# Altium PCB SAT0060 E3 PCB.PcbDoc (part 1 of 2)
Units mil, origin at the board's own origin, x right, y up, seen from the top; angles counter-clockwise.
Board outline 3780 x 2000 mil, 4 copper layers (Top Layer, L2_GND-Plane, L3_Sig-Layer, Bottom Layer), stack 61.2 mil thick; 136 components, 78 nets, 386 pads, 150 vias.
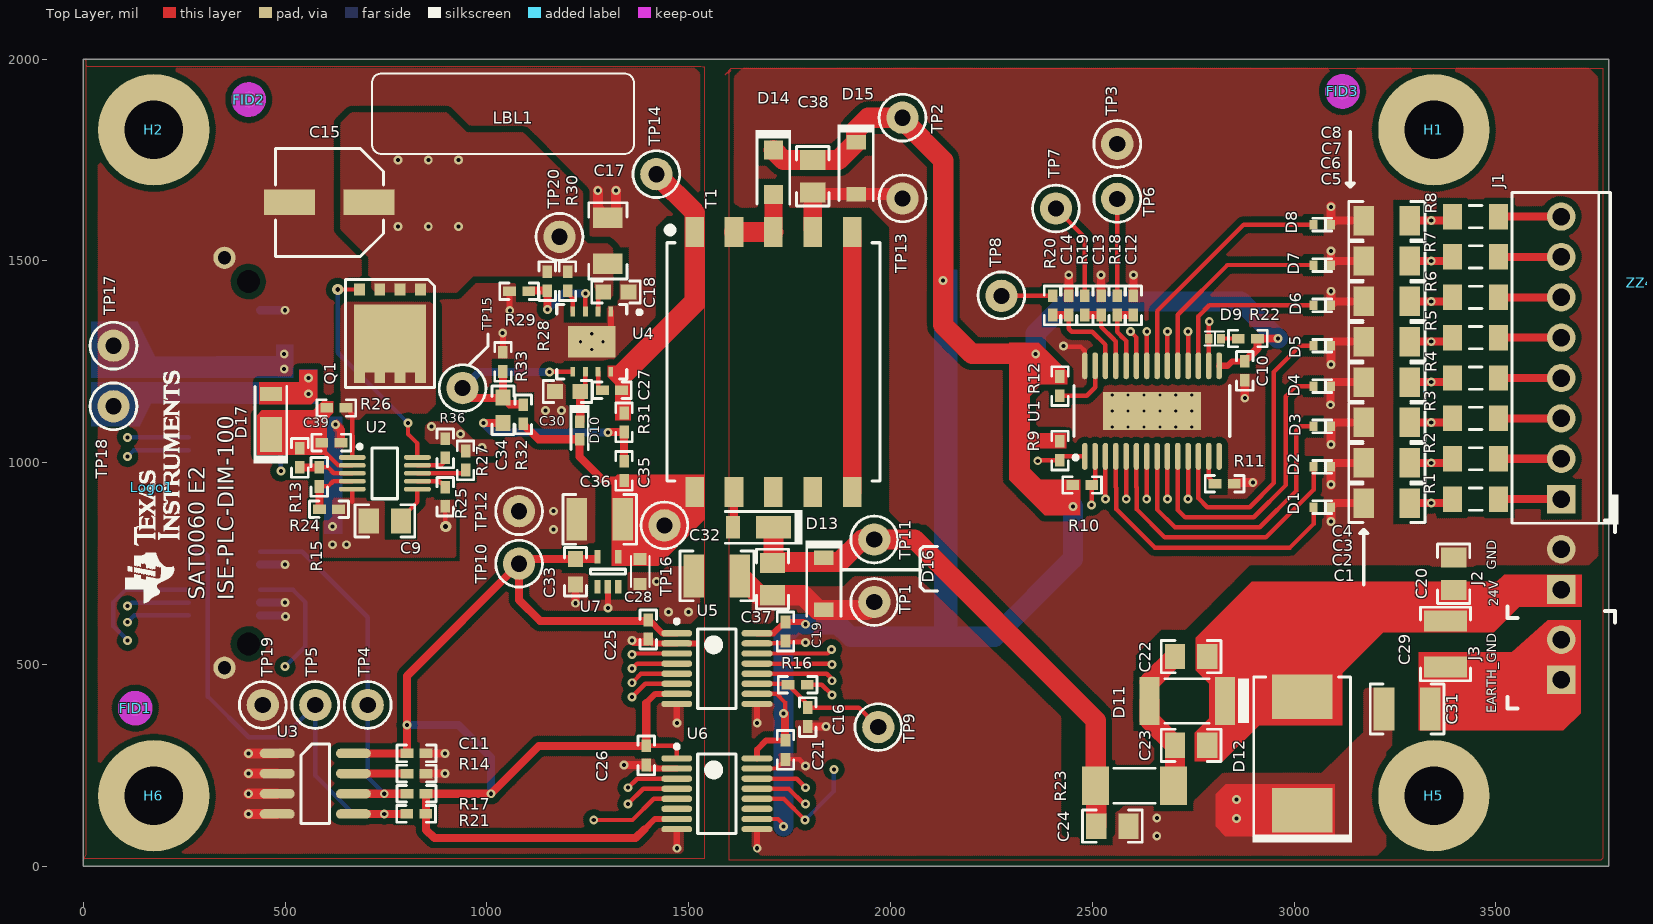
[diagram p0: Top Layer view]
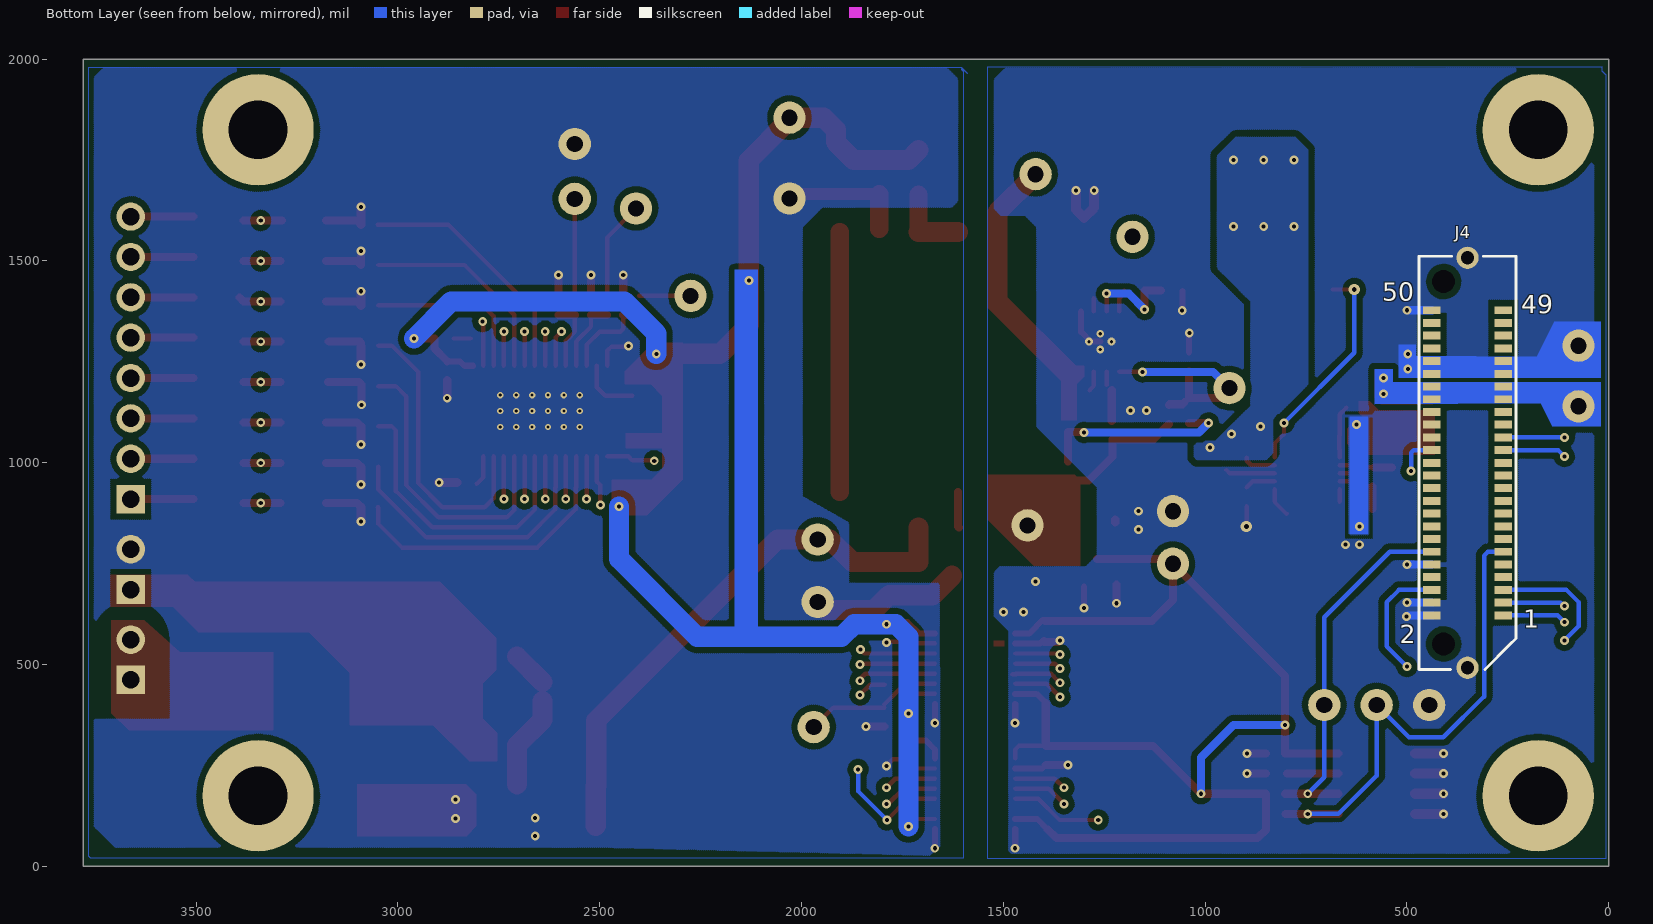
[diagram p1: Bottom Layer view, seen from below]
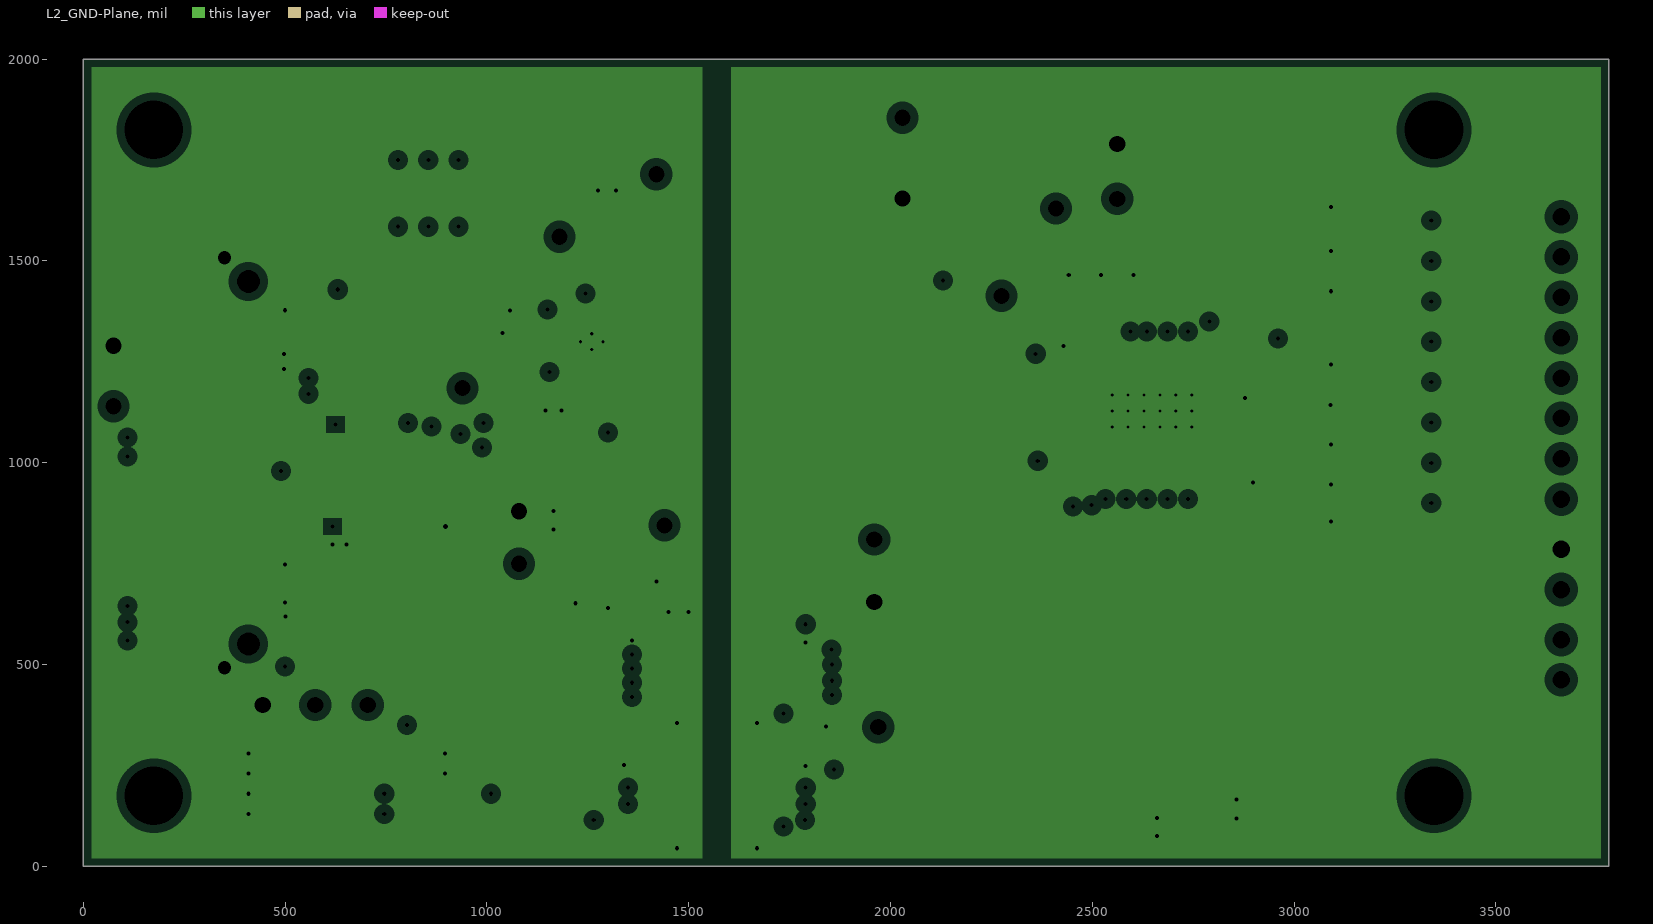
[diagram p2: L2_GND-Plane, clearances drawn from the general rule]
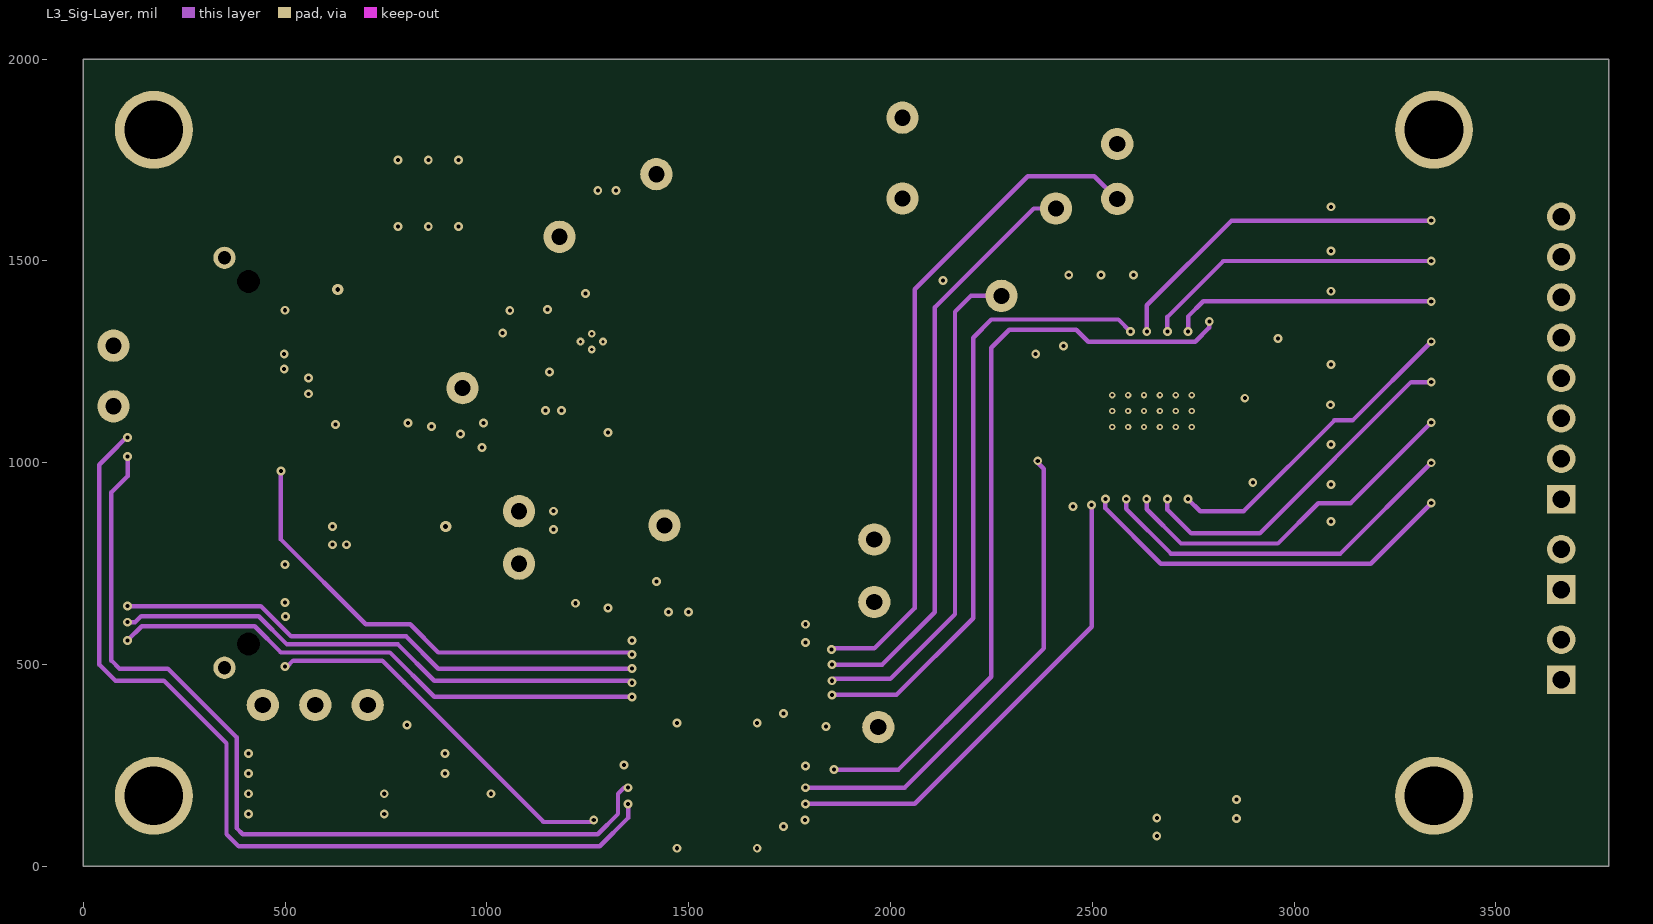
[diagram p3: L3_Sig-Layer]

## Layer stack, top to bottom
Top Layer: signal copper 1.4
Dielectric: prepreg 12.6, 370HR, Dk 4.8
L2_GND-Plane: plane copper 1.4, net (Multiple Nets)
Dielectric: core 30.4, 370HR, Dk 4.8
L3_Sig-Layer: signal copper 1.4
Dielectric: prepreg 12.6, FR-4, Dk 4.8
Bottom Layer: signal copper 1.4

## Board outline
0,0 3780,0 3780,2000 0,2000

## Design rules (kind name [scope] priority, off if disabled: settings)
AcuteAngle [All] p1: minimum=4.50000000000000E+0001 checktracksonly=FALSE
AssemblyTestPointUsage [All] p1: valid=2
Clearance "Clearance Earth ground" [InNet('EARTH_GND') vs InPolygon] p1: gap=60
Clearance "Poly Clearance" [InPolygon] p2: gap=15
Clearance Clearance_1 [All] p3: gap=7.8
Clearance Clearance_BoardEdge_MountingHoles [OnCopper and InComponentClass('Mounting Holes') vs IsKeepOut] p4: gap=20
Clearance Clearance_BoardEdge_Poly [OnCopper and InPoly vs IsKeepOut] p5: gap=20
Clearance Clearance_BoardEdge [OnCopper and Not InComponentClass('Logo') and not InComponentClass('FiducialMark') and not InRegion(1000,500,4000,800) vs IsKeepOut] p6: gap=20
ComponentClearance ComponentClearance_1 [HasFootprint('TI_Stacked_Overlay_Small_Vertical') vs InComponent('TP18')] p1: gap=0 collisioncheckmode=3 verticalgap=0 showdistances=FALSE
ComponentClearance ComponentClearance_Logo [InComponentClass(Logo) vs InComponent('TP18')] p2 off: gap=50 collisioncheckmode=3 verticalgap=0 showdistances=TRUE
ComponentClearance ComponentClearance_ScrewToNut [(HasFootprint('NY PMS 440 0025 PH')) vs (HasFootprint('Keystone_1902C'))] p3 off: gap=5 collisioncheckmode=3 verticalgap=10 showdistances=FALSE
ComponentClearance ComponentClearance_MountingHoles [InComponentClass('Mounting Holes')] p4 off: gap=250 collisioncheckmode=3 verticalgap=100000 showdistances=FALSE
ComponentClearance ComponentClearance_SmallPassives [HasFootprint('0201*') or HasFootprint('0402*') or HasFootprint('0508') or HasFootprint('0603*') or HasFootprint('0612') or HasFootprint('0805*') or HasFootprint('0815*') or HasFootprint('0830*') or HasFootprint('1206*') or HasFootprint('1210*') or HasFootprint('1808*') or HasFootprint('1812*') or HasFootprint('1825*') or HasFootprint('2010*') or HasFootprint('2220*') or HasFootprint('2225*') or HasFootprint('2512*') or HasFootprint('2728*') or HasFootprint('3518*') vs HasFootprint('0201*') or HasFootprint('0402*') or HasFootprint('0508') or HasFootprint('0603*') or HasFootprint('0612') or HasFootprint('0805*') or HasFootprint('0815*') or HasFootprint('0830*') or HasFootprint('1206*') or HasFootprint('1210*') or HasFootprint('1808*') or HasFootprint('1812*') or HasFootprint('1825*') or HasFootprint('2010*') or HasFootprint('2220*') or HasFootprint('2225*') or HasFootprint('2512*') or HasFootprint('2728*') or HasFootprint('3518*')] p5 off: gap=20 collisioncheckmode=3 verticalgap=10 showdistances=FALSE
ComponentClearance ComponentClearance_THtoSMT [IsThruComponent vs IsSMTComponent] p6 off: gap=100 collisioncheckmode=3 verticalgap=100000 showdistances=FALSE
ComponentClearance ComponentClearance_THtoTH [IsThruComponent vs IsThruComponent] p7 off: gap=118.11 collisioncheckmode=3 verticalgap=100000 showdistances=FALSE
ComponentClearance [All] p8: gap=5 collisioncheckmode=3 verticalgap=10 showdistances=TRUE
DiffPairsRouting [All] p1: maxlimit=100 minlimit=10 mostfreqgap=10 maxuncoupledlength=1000
FabricationTestPointUsage TestPointUsage [All] p1: valid=2 allowmultiple=FALSE
FabricationTestpoint Testpoint [All] p1: side=3 testpointundercomponent=TRUE minsize=40 maxsize=100 preferedsize=60 minholesize=0 maxholesize=40 preferedholesize=32 testpointgrid=1 allowsidetop=TRUE allowsidebottom=TRUE usegrid=TRUE gridtolerance=0.01
FanoutControl Fanout_LCC [IsLCC] p1: bgadir=Out bgaviamode=Centered fanoutstyle=Auto fanoutdirection=Alternating viagrid=1 // Fanout_LCC (Default Rule)
FanoutControl Fanout_BGA [IsBGA] p2: bgadir=Out bgaviamode=Centered fanoutstyle=Auto fanoutdirection=Alternating viagrid=1 // Fanout_BGA (Default Rule)
FanoutControl Fanout_Default [All] p4: bgadir=Out bgaviamode=Centered fanoutstyle=Auto fanoutdirection=Alternating viagrid=1 // Fanout_Default (Default Rule)
FanoutControl Fanout_Small [(CompPinCount < 5)] p5: bgadir=Out bgaviamode=Centered fanoutstyle=Auto fanoutdirection=OutThenIn viagrid=1 // Fanout_Small (Default Rule)
HoleSize [All] p1: absolutevalues=TRUE maxlimit=550 minlimit=5 maxpercent=80.000 minpercent=20.000
MinimumAnnularRing MinimumAnnularRing_2 [InComponent('U4')] p1: minimumring=3
MinimumAnnularRing MinimumAnnularRing_1 [InComponent('U1')] p2: minimumring=3
MinimumAnnularRing [All] p3: minimumring=6
MinimumSolderMaskSliver MinimumSolderMaskSliver_1 [InComponent('U2') OR  InComponent('U6') OR  InComponent('U5') OR  InComponent('U7')] p1: minsoldermaskwidth=1
MinimumSolderMaskSliver MinimumSolderMaskSliver_Logo [InComponentClass('Logo') vs InComponentClass('Logo')] p2: minsoldermaskwidth=0.7
MinimumSolderMaskSliver [All] p3: minsoldermaskwidth=5
PlaneClearance PlaneClearance_1 [All] p1: clearance=20
PlaneConnect [All] p1: planeconnectstyle=Direct reliefexpansion=10 reliefentries=4 reliefconductorwidth=10 reliefairgap=10
PolygonConnect [All] p1: connectstyle=Direct reliefconductorwidth=10 reliefentries=4 polygonreliefangle="90 Angle" airgapwidth=10
RoutingVias [All] p1: holewidth=12 width=28 viastyle="Through Hole" minholewidth=5 minwidth=7 maxholewidth=100 maxwidth=150
SMDToCorner [All] p1: distance=30000
SilkToSilkClearance [All] p1: silktosilkclearance=5
SilkscreenOverComponentPads SilkscreenOverComponentPads_4 [HasFootprint('SML-P12VTT86')] p1: minsilkscreentomaskgap=0
SilkscreenOverComponentPads SilkscreenOverComponentPads_3 [InComponent('C8')] p2: minsilkscreentomaskgap=3
SilkscreenOverComponentPads SilkscreenOverComponentPads_2 [HasFootprint('0402')] p3: minsilkscreentomaskgap=3
SilkscreenOverComponentPads SilkscreenOverComponentPads_1 [HasFootprint('SML-P12PTT86') OR HasFootprint('SML-P12VTT86')OR HasFootprint('0603')] p4: minsilkscreentomaskgap=0.3
SilkscreenOverComponentPads [All] p5: minsilkscreentomaskgap=5
SolderMaskExpansion [All] p1: expansion=3
Width [All] p1: maxlimit=100 minlimit=6 preferedwidth=10 checkconnectedcopper=TRUE
13 further rules are at their usual default settings.

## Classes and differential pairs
component class "SAT0060 Sheet1": C9 C11 C15 C17 C18 C27 C28 C30 C32 C33 C34 C35 C36 C37 C38 C39 D10 D13 D14 D15 D16 D17 J4 Q1 R13 R14 R15 R17 R21 R24 R25 R26 R27 R28 R29 R30 R31 R32 R33 R36 T1 TP1 TP2 TP3 TP4 TP5 TP10 TP11 TP12 TP13 TP14 TP15 TP16 TP17 TP18 TP19 TP20 U2 U3 U4 U7
component class Logo: Logo1
component class Hardware_ANSI-B: FID1 FID2 FID3 H1 H2 H5 H6 LBL1 Logo1 ZZ1 ZZ2 ZZ3 ZZ4
component class FiducialMark: FID1 FID2 FID3
component class AssemblyNote: ZZ1 ZZ2 ZZ3 ZZ4
component class Label: LBL1
component class "SAT0060 Sheet2": C1 C2 C3 C4 C5 C6 C7 C8 C10 C12 C13 C14 C16 C19 C20 C21 C22 C23 C24 C25 C26 C29 C31 D1 D2 D3 D4 D5 D6 D7 D8 D9 D11 D12 J1 J2 J3 R1 R2 R3 R4 R5 R6 R7 R8 R9 R10 R11 R12 R16 R18 R19 R20 R22 R23 TP6 TP7 TP8 TP9 U1 U5 U6

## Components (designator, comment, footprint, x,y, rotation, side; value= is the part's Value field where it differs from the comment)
C1 "202R18W102KV4E" 1206 3230,900 r180 top
C2 "202R18W102KV4E" 1206 3230,1000 r180 top
C3 "202R18W102KV4E" 1206 3230,1100 r180 top
C4 "202R18W102KV4E" 1206 3230,1200 r180 top
C5 "202R18W102KV4E" 1206 3230,1300 r180 top
C6 "202R18W102KV4E" 1206 3230,1400 r180 top
C7 "202R18W102KV4E" 1206 3230,1500 r180 top
C8 "202R18W102KV4E" 1206 3230,1600 r180 top
C9 "0805YC474JAT2A" 0805_HV 747.35,855.82 r180 top
C10 "GRM155R71C104KA88D" 0402 2877.93,1227.87 r270 top
C11 "GRM155R71C104KA88D" 0402 825.79,280 r0 top
C12 "GRM1555C1H470JZ01" 0402 2601.79,1390 r90 top
C13 "GRM1555C1H470JZ01" 0402 2521.79,1390 r90 top
C14 "GRM1555C1H470JZ01" 0402 2441.79,1390 r90 top
C15 "EEE-FK1H220P" SM_RADIAL_D 609.95,1645 r180 top
C16 "GRM1555C1H470JZ01" 0402 1795,370 r270 top
C17 "GRM31CR72A105KA01L" 1206 1300,1550 r90 top
C18 "GRM188R72A104KA35D" 0603#1 1320,1423 r0 top
C19 "GRM155R71C104KA88D" 0402 1740,582 r270 top
C20 "GRM21AR72A224KAC5L" 0805_HV 3395.32,725 r90 top
C21 "GRM155R71C104KA88D" 0402 1740,288.62 r270 top
C22 "GRM21AR72A224KAC5L" 0805_HV 2745,520 r0 top
C23 "GRM21AR72A224KAC5L" 0805_HV 2745,300 r0 top
C24 "GRM21AR72A224KAC5L" 0805_HV 2550,100 r0 top
C25 "GRM155R71C104KA88D" 0402 1400,587 r270 top
C26 "GRM155R71C104KA88D" 0402 1395,275 r270 top
C27 "C1005X7R1C103K" 0402 1310,1180 r0 top
C28 "GRM188R71E104KA01D" 0603#2 1380,730.31 r90 top
C29 "Used in BOM report" 1210 3375.32,551 r270 top
C30 "C1608X7R1C105K" 0603#1 1200,1177 r180 top
C31 "Used in BOM report" 1210 3280,390 r180 top
C32 "Used in BOM report" 1210 1570,720 r180 top
C33 "GRM188R71C105KA12D" 0603#1 1220,730.31 r270 top
C34 "GRM188R71E102KA01D" 0603#1 1040,1130 r90 top
C35 "GRM155R71H103KA88D" 0402 1340,980 r90 top
C36 "GRM32ER71E226KE15L" 1210 1280,860 r180 top
C37 "GRM21BR71E225KA73L" 0805_HV 1707.8,711.8 r270 top
C38 "GRM21BR71E225KA73L" 0805_HV 1807.64,1710 r270 top
C39 "GRM155R72A102KA01D" 0402 615,1050 r0 top
D1 "SML-P12PTT86" SML-P12PTT86 3070.01,890 r0 top
D2 "SML-P12PTT86" SML-P12PTT86 3070.01,990 r0 top
D3 "SML-P12PTT86" SML-P12PTT86 3070.01,1090 r0 top
D4 "SML-P12PTT86" SML-P12PTT86 3070.01,1190 r0 top
D5 "SML-P12PTT86" SML-P12PTT86 3070.01,1290 r0 top
D6 "SML-P12PTT86" SML-P12PTT86 3070.01,1390 r0 top
D7 "SML-P12PTT86" SML-P12PTT86 3070.01,1490 r0 top
D8 "SML-P12PTT86" SML-P12PTT86 3070.01,1590.02 r0 top
D9 "SML-P12VTT86" SML-P12VTT86 2801.71,1307.87 r180 top
D10 "SDM10U45-7-F" SOD-523 1230,1080 r270 top
D11 "BYM10-1000-E3/97" DO-213AB 2735,410 r180 top
D12 "SMCJ33CA" SMC 3020,280 r90 top
D13 "DFLS1200-7" powerDI123 1660,840 r180 top
D14 "PMEG6010CEH,115" SOD-123F 1710,1720 r270 top
D15 "MMSZ5234B-7-F" SOD-123 1915.02,1730 r270 top
D16 "MMSZ5254B-7-F" SOD-123 1835,700 r270 top
D17 "DFLS1200-7" powerDI123 465,1120 r90 top
FID1 "Fiducial" Fiducial10-20 129,392 r90 top
FID2 "Fiducial" Fiducial10-20 410,1900 r0 top
FID3 "Fiducial" Fiducial10-20 3120,1920 r0 top
H1 "29311" Keystone29311#1 3350,1825 r0 top
H2 "29311" Keystone29311#2 175,1825 r0 top
H5 "29311" Keystone29311#1 3350,175 r0 top
H6 "29311" Keystone29311#2 175,175 r0 top
J1 "1725711" CONN_1725711 3662,1260 r90 top locked
J2 "1725656" CONN_1725656 3662,736 r90 top
J3 "1725656" CONN_1725656 3662,512 r90 top
J4 "ERF8-025-05.0-L-DV-K-TR" CONN_ERF8-025-05_0-L-DV-L-TR 350,1000 r270 bottom
LBL1 "Size: 0.65\" x 0.20 \"" Label_650x200 1040,1865 r180 top
Logo1 "Texas Instruments" TI_Stacked_Overlay_Small_Vertical 170,940 r0 top
Q1 "CSD18537NQ5A" TRANS_NexFET_Q5A 760,1320 r270 top
R1 "MMA02040C1201FB300" MMA0204 3450,910 r180 top
R2 "MMA02040C1201FB300" MMA0204 3450,1010 r180 top
R3 "MMA02040C1201FB300" MMA0204 3450,1110 r180 top
R4 "MMA02040C1201FB300" MMA0204 3450,1210 r180 top
R5 "MMA02040C1201FB300" MMA0204 3450,1310 r180 top
R6 "MMA02040C1201FB300" MMA0204 3450,1410 r180 top
R7 "MMA02040C1201FB300" MMA0204 3450,1510 r180 top
R8 "MMA02040C1201FB300" MMA0204 3450,1610 r180 top
R9 "CRCW040210K0FKED" 0402 2420,1030 r90 top
R10 "CRCW040210K0FKED" 0402 2475,945 r180 top
R11 "CRCW040244K2FKED" 0402 2827.93,948.19 r180 top
R12 "CRCW040210K0FKED" 0402 2420,1190 r270 top
R13 "CRCW040247K5FKED" 0402 537,1012.22 r90 top
R14 "CRCW04020000Z0ED" 0402 825.79,230 r0 top
R15 "CRCW040211K3FKED" 0402 585,965 r90 top
R16 "CRCW040280R6FKED" 0402 1770,450 r180 top
R17 "CRCW04021K50FKED" 0402 825.79,180 r0 top
R18 "CRCW040280R6FKED" 0402 2561.79,1390 r90 top
R19 "CRCW040280R6FKED" 0402 2481.79,1390 r90 top
R20 "CRCW040280R6FKED" 0402 2401.79,1390 r90 top
R21 "CRCW04021K50FKED" 0402 825,130 r0 top
R22 "CRCW04021K15FKED" 0402 2885.71,1307.87 r0 top
R23 "MMB02070C5609FB200" MMB0207 2605,200 r0 top
R24 "CRCW04024K64FKED" 0402 609,885 r180 top
R25 "CRCW040222K6FKED" 0402 897.35,915.82 r90 top
R26 "Used in BOM report" 0402 627.35,1135.82 r0 top
R27 "CRCW0402100KFKED" 0402 947.35,1005.82 r270 top
R28 "CRCW040249K9FKED" 0402 1150,1450 r90 top
R29 "CRCW04026K34FKED" 0402 1080,1425 r0 top
R30 "CRCW0402340KFKED" 0402 1200,1450 r90 top
R31 "CRCW040220K0FKED" 0402 1340,1100 r270 top
R32 "CRCW0402105KFKED" 0402 1090,1120 r270 top
R33 "CRCW040220K0FKED" 0402 1040,1250 r270 top
R36 "CRCW04020000Z0ED" 0402 897.35,1035.82 r270 top
T1 "750313995" WURTH_750313995 1710,1250 r0 top
TP1 "5001" Keystone5001 1960,655 r0 top
TP2 "5002" Keystone5002 2030,1855 r0 top
TP3 "5001" Keystone5001 2562,1790 r0 top
TP4 "5003" Keystone5003#1 705,400 r0 top
TP5 "5003" Keystone5003#1 575,400 r0 top
TP6 "5003" Keystone5003#1 2562,1654 r0 top
TP7 "5003" Keystone5003#1 2410,1630 r0 top
TP8 "5003" Keystone5003#2 2275,1415 r0 top
TP9 "5003" Keystone5003#1 1970,345 r0 top
TP10 "5002" Keystone5002 1080,750 r0 top
TP11 "5002" Keystone5002 1960,810 r0 top
TP12 "5001" Keystone5001 1080,880 r0 top
TP13 "5001" Keystone5001 2030,1655 r0 top
TP14 "5004" Keystone5004 1420,1715 r0 top
TP15 "5004" Keystone5004 940,1185 r0 top
TP16 "5002" Keystone5002 1440,845 r0 top
TP17 "5001" Keystone5001 75,1290 r0 top
TP18 "5002" Keystone5002 75,1140 r0 top
TP19 "5001" Keystone5001 445,400 r0 top
TP20 "5002" Keystone5002 1180,1560 r0 top
U1 "SN65HVS885PWP" PWP0028E_N 2647.93,1128.19 r90 top
U2 "LM5069MM-2" MUB10A_N 747.35,974.01 r0 top
U3 "AT24C02C-SSHM-B" SOIC-8 575,205 r0 top
U4 "LM5017SD/NOPB" NGU0008B 1260,1300 r270 top
U5 "ISO7141CCDBQ" DBQ0016A_N 1570,490 r0 top
U6 "ISO7131CCDBQ" DBQ0016A_N 1570,180 r0 top
U7 "TPS71533DCK" DCK0005A_N 1300,730.31 r90 top
ZZ1 "This Assembly Note is for PCB labels only" AssemblyNoteLabel 4298,246 r90 top
ZZ2 "These assemblies are ESD sensitive, ESD precautions shall be observed." AssemblyNote 4158,2706 r90 top
ZZ3 "These assemblies must be clean and free from flux and all contaminants. Use of no clean flux is not acceptable." AssemblyNote 4008,1156 r90 top
ZZ4 "These assemblies must comply with workmanship standards IPC-A-610 Class 2., unless otherwise specified." AssemblyNote 3858,1446 r90 top

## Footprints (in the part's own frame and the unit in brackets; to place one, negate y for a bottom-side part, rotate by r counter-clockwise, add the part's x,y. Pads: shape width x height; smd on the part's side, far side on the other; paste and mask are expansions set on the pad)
0402 [mm] "0402 from SM-752 data"
  rect 0.8x0.6 smd: 1(-0.6,0) 2(0.6,0)
  silkscreen extent -1.22,-0.52 1.22,0.52, body extent -0.55,-0.3 0.55,0.3, height 0.6
0603#1 [mm] "0603 from SM-752 data"
  rect 1x0.95 smd: 1(-0.8,0) 2(0.8,0)
  silkscreen extent -1.52,-0.69 1.52,0.69, body extent -0.87,-0.47 0.87,0.47, height 0.85
0603#2 [mm]
  rect 0.762x0.813 smd mask+0.051: 1(-0.787,0) 2(0.787,0)
  silkscreen extent -0.97,-0.58 0.97,0.58, body extent -0.87,-0.47 0.87,0.47, height 0.85
0805_HV [mil] "0805 with 30mil clearance between pads"
  rect 50x63 smd: 1(-40,0) 2(40,0)
  silkscreen extent -74,-40 74,40, body extent -43,-29 43,29, height 43
1206 [mm] "1206 from SM-752 data"
  rect 1.3x1.85 smd: 1(-1.45,0) 2(1.45,0)
  silkscreen extent -2.4,-1.21 2.4,1.21, body extent -1.7,-0.9 1.7,0.9, height 1.35
1210 [mm] "1210 from SM-752 data"
  rect 1.3x2.7 smd: 1(-1.45,0) 2(1.45,0)
  silkscreen extent -2.32,-1.57 2.32,1.57, body extent -1.7,-1.35 1.7,1.35, height 1.35
AssemblyNote [mil] "Assembly Note"
AssemblyNoteLabel [mil] "Assembly Note for PCB Labels"
CONN_1725656 [mm] "Phoenix Contact"
  rect 1.8x1.8 hole 1.1: 1(-1.27,0)
  round 1.8 hole 1.1: 2(1.27,0)
  silkscreen extent -3.08,-3.37 3.08,3.37, body extent -2.77,-3.1 2.77,3.1, height 8.52
CONN_1725711 [mm] "Phoenix Contact"
  rect 1.78x1.78 hole 1.1: 1(-8.89,0)
  round 1.78 hole 1.1: 2(-6.35,0) 3(-3.81,0) 4(-1.27,0) 5(1.27,0) 6(3.81,0) 7(6.35,0) 8(8.89,0)
  silkscreen extent -10.49,-3.6 10.4,3.1, body extent -10.39,-3.1 10.39,3.1, height 8.52
CONN_ERF8-025-05_0-L-DV-L-TR [mm] "Samtec 25X2 Header"
  rect 0.5x1.1 smd mask+0: 1(9.6,2.25) 2(9.6,-2.25) 3(8.8,2.25) 4(8.8,-2.25) 5(8,2.25) 6(8,-2.25) 7(7.2,2.25) 8(7.2,-2.25) 9(6.4,2.25) 10(6.4,-2.25) 11(5.6,2.25) 12(5.6,-2.25) 13(4.8,2.25) 14(4.8,-2.25) 15(4,2.25) 16(4,-2.25) 17(3.2,2.25) 18(3.2,-2.25) 19(2.4,2.25) 20(2.4,-2.25) 21(1.6,2.25) 22(1.6,-2.25) 23(0.8,2.25) 24(0.8,-2.25) 25(0,2.25) 26(0,-2.25) 27(-0.8,2.25) 28(-0.8,-2.25) 29(-1.6,2.25) 30(-1.6,-2.25) 31(-2.4,2.25) 32(-2.4,-2.25) 33(-3.2,2.25) 34(-3.2,-2.25) 35(-4,2.25) 36(-4,-2.25) 37(-4.8,2.25) 38(-4.8,-2.25) 39(-5.6,2.25) 40(-5.6,-2.25) 41(-6.4,2.25) 42(-6.4,-2.25) 43(-7.2,2.25) 44(-7.2,-2.25) 45(-8,2.25) 46(-8,-2.25) 47(-8.8,2.25) 48(-8.8,-2.25) 49(-9.6,2.25) 50(-9.6,-2.25)
  round 1.4 hole 0.838: MH1(12.9,0) MH2(-12.9,0)
  round 1 hole 1.45 unplated mask+0.508: MH3(11.4,-1.5) MH4(-11.4,-1.5)
  silkscreen extent -13,-3.05 13,3.05, body extent -13.03,-2.8 13.03,2.8, height 5.3
DBQ0016A_N [mm] "SOP, 16-Leads, Body 4.9x3.9mm, Pitch 0.635mm, IPC Medium Density"
  oval 1.95x0.4 smd: 1(-2.525,2.222) 2(-2.525,1.587) 3(-2.525,0.953) 4(-2.525,0.318) 5(-2.525,-0.318) 6(-2.525,-0.953) 7(-2.525,-1.587) 8(-2.525,-2.222) 9(2.525,-2.222) 10(2.525,-1.587) 11(2.525,-0.953) 12(2.525,-0.318) 13(2.525,0.318) 14(2.525,0.953) 15(2.525,1.587) 16(2.525,2.222)
  silkscreen extent -2.65,-2.5 1.2,3.1, body extent -1.99,-2.5 2,2.5, height 1.76
DCK0005A_N [mm] "SOT353, 5-Leads, Body 2x1.3mm, Pitch 0.65mm, Lead Span 2.1mm, IPC Medium Density"
  rect 0.85x0.4 smd: 1(-0.95,0.65) 2(-0.95,0) 3(-0.95,-0.65) 4(0.95,-0.65) 5(0.95,0.65)
  silkscreen extent -0.15,-1.1 0.15,1.1, body extent -1.14,-1 1.14,1, height 0.94
DO-213AB [mm] "VISHAY"
  rect 1.25x3 smd: 1(-2.375,0) 2(2.375,0)
  silkscreen extent -3.9,-1.4 1.4,1.4, body extent -2.6,-1.34 2.6,1.33, height 2.67
Fiducial10-20 [mm]
  round 1 smd paste-0.5 mask+0.5: 1(0,0)
  Top Layer keep-out circle w1.178: c0,0 r0.5
Keystone5001 [mil] "For Keystone 500x miniature loop terminals"
  round 80 hole 40: 1(0,0)
  silkscreen extent -58,-58 58,58, body extent -49,-49 49,49, height 182
Keystone5002 [mil] "For Keystone 500x miniature loop terminals"
  round 80 hole 40: 1(0,0)
  silkscreen extent -58,-58 58,58, body extent -49,-49 49,49, height 182
Keystone5003#1 [mil] "For Keystone 500x miniature loop terminals"
  round 80 hole 40: 1(0,0)
  silkscreen extent -58,-58 58,58, body extent -49,-49 49,49, height 182
Keystone5003#2 [mil] "For Keystone 500x miniature loop terminals"
  round 80 hole 40: 1(0,-1.38)
  silkscreen extent -58,-58 58,58, body extent -49,-49 49,49, height 182
Keystone5004 [mil] "For Keystone 500x miniature loop terminals"
  round 80 hole 40: 1(0,0)
  silkscreen extent -58,-58 58,58, body extent -49,-49 49,49, height 182
Keystone29311#1 [mm] "Srcew, Pan HeadM5x0.5 mm, Zinc Plated  6.0mm L"
  round 7 / inner round 4.9 / far side round 7 hole 3.7: 1(-0.09,0)
  body extent -2.7,-2.7 2.7,2.7, height 1.72
Keystone29311#2 [mm] "Srcew, Pan HeadM5x0.5 mm, Zinc Plated  6.0mm L"
  round 7 / inner round 4.9 / far side round 7 hole 3.7: 1(0,0)
  body extent -2.7,-2.7 2.7,2.7, height 1.72
Label_650x200 [mil] "Thermal Transfer Label"
  round 1 on Mech13: 0(0,0)
  silkscreen extent -325,-100 325,100, body extent -326,-101 326,101, height 1
MMA0204 [mm] "Vishay Beyschlag"
  rect 1.2x1.6 smd: 1(-1.45,0) 2(1.45,0)
  silkscreen extent -0.4,-0.7 0.4,0.7, body extent -1.8,-0.7 1.8,0.7, height 1.4
MMB0207 [mm] "Vishay Beyschlag"
  rect 1.7x2.4 smd: 1(-2.45,0) 2(2.45,0)
  silkscreen extent -1.3,-1.1 1.3,1.1, body extent -2.98,-1.1 2.98,1.1, height 2.2
MUB10A_N [mm] "TSSOP, 10-Leads, Body 3x3mm, Pitch 0.5mm, IPC Medium Density"
  oval 1.7x0.3 smd: 1(-2.05,1) 2(-2.05,0.5) 3(-2.05,0) 4(-2.05,-0.5) 5(-2.05,-1) 6(2.05,-1) 7(2.05,-0.5) 8(2.05,0) 9(2.05,0.5) 10(2.05,1)
  silkscreen extent -1.71,-1.6 0.8,1.8, body extent -1.6,-1.6 1.6,1.6, height 1.09
NGU0008B [mm] "SON, 8-Leads, Body 4x4mm, Pitch 0.8mm"
  rect 0.6x0.3 smd mask+0.051: 1(-1.9,1.2) 2(-1.9,0.4) 3(-1.9,-0.4) 4(-1.9,-1.2) 5(1.9,-1.2) 6(1.9,-0.4) 7(1.9,0.4) 8(1.9,1.2)
  rect 1.98x3 smd paste-1.5 mask+0.051: 9(0,0)
  silkscreen extent -2.35,-2.2 2.35,3.12, body extent -2.05,-2.05 2.05,2.05, height 0.8
powerDI123 [mm] "Diodes Inc recommended land pattern, document number DS30628 Rev. 6-2"
  rect 2.2x1.4 smd: 1(-1.275,0)
  rect 0.9x1.4 smd: 2(1.275,0)
  silkscreen extent -3.1,-1.09 1.76,1.09, body extent -2.38,-0.97 1.52,0.96, height 1
PWP0028E_N [mm] "TSOP, 28-Leads, Body 9.7x4.4mm, Pitch 0.65mm, Exposed Pad, IPC Medium Density"
  oval 1.7x0.35 smd: 1(-2.85,4.225) 2(-2.85,3.575) 3(-2.85,2.925) 4(-2.85,2.275) 5(-2.85,1.625) 6(-2.85,0.975) 7(-2.85,0.325) 8(-2.85,-0.325) 9(-2.85,-0.975) 10(-2.85,-1.625) 11(-2.85,-2.275) 12(-2.85,-2.925) 13(-2.85,-3.575) 14(-2.85,-4.225) 15(2.85,-4.225) 16(2.85,-3.575) 17(2.85,-2.925) 18(2.85,-2.275) 19(2.85,-1.625) 20(2.85,-0.975) 21(2.85,-0.325) 22(2.85,0.325) 23(2.85,0.975) 24(2.85,1.625) 25(2.85,2.275) 26(2.85,2.925) 27(2.85,3.575) 28(2.85,4.225)
  rect 2.4x6.17 smd: 29(0,0)
  silkscreen extent -3.05,-4.9 1.6,4.92, body extent -3.21,-4.85 3.21,4.85, height 0.98
SM_RADIAL_D [mm] "6.3 x 5.8mm:  Panasonic D"
  rect 3.2x1.6 smd: 1(-2.5,0) 2(2.5,0)
  silkscreen extent -3.4,-3.4 3.4,3.4, body extent -3.41,-3.41 3.41,3.41, height 6.1
SMC [mil] "Molded Diode, 2-Leads, Body 6.9x5.8mm, IPC Medium Density, based on OnSemi component dimensions and land patterns"
  rect 110x150 smd: 1(-140.49,0) 2(140.49,0)
  silkscreen extent -221,-124 189,123, body extent -156,-116 156,116, height 91
SML-P12PTT86 [mm]
  rect 0.5x0.6 smd mask+0.05: 1(-0.55,0) 2(0.55,0)
  silkscreen extent -0.6,-0.4 0.6,0.4, body extent -0.5,-0.25 0.51,0.25, height 0.45
SML-P12VTT86 [mm]
  rect 0.5x0.6 smd mask+0.05: 1(-0.45,0) 2(0.331,0)
  silkscreen extent -0.63,-0.45 0.6,0.45, body extent -0.5,-0.3 0.5,0.3, height 0.25
SOD-123 [mm] "On Semi recommended land pattern"
  rect 0.915x1.22 smd: 1(-1.637,0) 2(1.637,0)
  silkscreen extent -2.74,-1.17 2.03,1.17, body extent -1.93,-0.9 1.93,0.9, height 1.35
SOD-123F [mm] "NXP recommended land pattern"
  rect 1.2x1.2 smd paste-0.05: 1(-1.4,0) 2(1.4,0)
  silkscreen extent -2.64,-1.12 2.01,1.12, body extent -1.8,-0.85 1.8,0.85, height 1.2
SOD-523 [mm] "NXP Semiconductor recommended land pattern, nominal STEP model"
  rect 0.8x0.6 smd paste-0.05: 1(-0.55,0) 2(0.55,0)
  silkscreen extent -1.6,-0.64 1.2,0.63, body extent -0.8,-0.4 0.8,0.4, height 0.72
SOIC-8 [mm] "duplicate of SO-8.  SOIC, 8-Leads, Body 5.0x4.0mm (max), Pitch 1.27mm, IPC Medium Density"
  oval 2.2x0.6 smd: 1(-2.4,1.905) 2(-2.4,0.635) 3(-2.4,-0.635) 4(-2.4,-1.905) 5(2.4,-1.905) 6(2.4,-0.635) 7(2.4,0.635) 8(2.4,1.905)
  silkscreen extent -0.9,-2.5 0.9,2.5, body extent -3,-2.45 3,2.45, height 1.63
TI_Stacked_Overlay_Small_Vertical [mil]
  silkscreen extent -66,-288 69,288
TRANS_NexFET_Q5A [mm] "TI recommended land pattern (nominal) M0139-01"
  rect 0.75x0.675 smd paste-0.1 mask+0.051: 1(-2.776,1.917) 2(-2.776,0.639) 3(-2.776,-0.639) 4(-2.776,-1.917)
  rect 0.655x0.675 smd paste-0.1 mask+0.051: 5(2.776,-1.917) 6(2.776,-0.639) 7(2.776,0.639) 8(2.776,1.917)
  rect 4.295x4.51 smd paste-2.2 mask+0.051: 9(0.301,0)
  silkscreen extent -3.4,-2.8 3.4,2.8, body extent -3.05,-2.5 3.05,2.5, height 1.11
WURTH_750313995 [mm] "WURTH"
  rect 1.17x1.88 smd: 1(-4.96,8.18) 2(-2.48,8.18) 3(0,8.18) 4(2.48,8.18) 5(4.96,8.18) 6(4.96,-8.18) 7(2.48,-8.18) 8(0,-8.18) 9(-2.48,-8.18) 10(-4.96,-8.18)
  silkscreen extent -6.7,-7.5 6.7,8.5, body extent -6.73,-8.9 6.73,8.9, height 12.7

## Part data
C1 C2 C3 C4 C5 C6 C7 C8: "CAP, CERM, 1000pF, 2KV 10% X7R 1206"
C9: "CAP, CERM, 0.47uF, 16V, +/-5%, X7R, 0805"
C10 C11 C19 C21 C25 C26: "CAP, CERM, 0.1uF, 16V, +/-10%, X7R, 0402"
C12 C13 C14 C16: "CAP, CERM, 47pF, 50V, +/-5%, C0G/NP0, 0402"
C15: "CAP, AL, 22uF, 50V, +/-20%, 0.88 ohm, SMD"
C17: "CAP, CERM, 1uF, 100V, +/-10%, X7R, 1206"
C18: "CAP, CERM, 0.1uF, 100V, +/-10%, X7R, 0603"
C20 C22 C23 C24: "CAP, CERM, 0.22uF, 100V, +/-10%, X7R, 0805"
C27: "CAP, CERM, 0.01uF, 16V, +/-10%, X7R, 0402"
C28: "CAP, CERM, 0.1uF, 25V, +/-10%, X7R, 0603"
C29 C31 C32: library part Capacitor, "CAP, CERM, xxxF, xxV, [TempCo], xx%, [PackageReference]"
C30 C33: "CAP, CERM, 1uF, 16V, +/-10%, X7R, 0603"
C34: "CAP, CERM, 1000pF, 25V, +/-10%, X7R, 0603"
C35: "CAP, CERM, 0.01uF, 50V, +/-10%, X7R, 0402"
C36: "CAP, CERM, 22uF, 25V, +/-10%, X7R, 1210"
C37 C38: "CAP, CERM, 2.2uF, 25V, +/-10%, X7R, 0805"
C39: "CAP, CERM, 1000pF, 100V, +/-10%, X7R, 0402"
D1 D2 D3 D4 D5 D6 D7 D8: "LED GREEN 0.2MM 13MCD 0402 SMD"
D9: "LED RED 0.2MM 60MCD 0402 SMD"
D10: "Diode, Schottky, 45V, 0.1A, SOD-523"
D11: "Diode, P-N, 1000V, 1A, 2.67x5.2mm"
D12: "Diode, TVS, Bi, 33V, 1500W, SMC"
D13 D17: "Diode, Schottky, 200V, 1A, PowerDI123"
D14: "Diode, Schottky, 60V, 1A, SOD-123F"
D15: "Diode, Zener, 6.2V, 500mW, SOD-123"
D16: "Diode, Zener, 27V, 500mW, SOD-123"
FID1 FID2 FID3: "Fiducial mark.  There is nothing to buy or mount."
H1 H2 H5 H6: "Screw Pan Head M3"
J1: "Terminal Block, 8x1, 2.54 mm, TH"
J2 J3: "Header, 2 Pos, 6A, 63V, TH"
J4: "Receptacle, 0.8mm, 25x2, SMT"
LBL1: library part THT-14-423-10, "Thermal Transfer Printable Labels, 0.650\" W x 0.200\" H - 10,000 per roll"
Logo1: library part TI_Logo, "Texas Instrument Corporate Signature"
Q1: "MOSFET, N-CH, 60V, 50A, SON 5x6mm"
R1 R2 R3 R4 R5 R6 R7 R8: "RES, 1.20k ohm, 1%, 0.25W, 1.4x3.6mm"
R9 R10 R12: "RES, 10.0k ohm, 1%, 0.063W, 0402"
R11: "RES, 44.2k ohm, 1%, 0.063W, 0402"
R13: "RES, 47.5k ohm, 1%, 0.063W, 0402"
R14 R36: "RES, 0 ohm, 5%, 0.063W, 0402"
R15: "RES, 11.3k ohm, 1%, 0.063W, 0402"
R16 R18 R19 R20: "RES, 80.6 ohm, 1%, 0.063W, 0402"
R17 R21: "RES, 1.50k ohm, 1%, 0.063W, 0402"
R22: "RES, 1.15k ohm, 1%, 0.063W, 0402"
R23: "RES, 56.0 ohm, 1%, 0.4W, 2.2x5.8mm"
R24: "RES, 4.64k ohm, 1%, 0.063W, 0402"
R25: "RES, 22.6k ohm, 1%, 0.063W, 0402"
R26: library part Resistor, "RES, xxx ohm, x%, xW, [PackageReference]"
R27: "RES, 100k ohm, 1%, 0.063W, 0402"
R28: "RES, 49.9k ohm, 1%, 0.063W, 0402"
R29: "RES, 6.34k ohm, 1%, 0.063W, 0402"
R30: "RES, 340k ohm, 1%, 0.063W, 0402"
R31 R33: "RES, 20.0k ohm, 1%, 0.063W, 0402"
R32: "RES, 105k ohm, 1%, 0.063W, 0402"
T1: "Transformer, 50uH, SMT"
TP1 TP3 TP12 TP13 TP17 TP19: "Test Point, Miniature, Black, TH"
TP2 TP10 TP11 TP16 TP18 TP20: "Test Point, Miniature, White, TH"
TP4 TP5 TP6 TP7 TP8 TP9: "Test Point, Miniature, Orange, TH"
TP14 TP15: "Test Point, Miniature, Yellow, TH"
U1: "34 V, Digital-Input Serializer for 5V Systems, PWP0028E"
U2: "Positive High Voltage Hot Swap / Inrush Current Controller with Power Limiting, 10-pin MSOP"
U3: "IC, EEPROM, 2KBIT, 1MHZ, SOIC-8"
U4: "100V, 600mA Constant On-Time Synchronous Buck Regulator, NGU0008B"
U5: "4242-VPK Small-Footprint and Low-Power Quad Channels Digital Isolators, DBQ0016A"
U6: "4242-VPK Small-Footprint and Low-Power Triple Channels Digital Isolators, DBQ0016A"
U7: "50 mA, 24 V, 3.2-mA Supply Current Low-Dropout Linear Regulator, DCK0005A"
ZZ1: library part AssemblyNoteLabel
ZZ2 ZZ3 ZZ4: library part AssemblyNote

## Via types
v1: diameter 22, hole 10, Top Layer to Bottom Layer, 126 vias
v2: diameter 15.75, hole 7.87, Top Layer to Bottom Layer, 18 vias
v3: diameter 19.68, hole 7.87, Top Layer to Bottom Layer, 4 vias
v4: diameter 28, hole 12, Top Layer to Bottom Layer, 2 vias

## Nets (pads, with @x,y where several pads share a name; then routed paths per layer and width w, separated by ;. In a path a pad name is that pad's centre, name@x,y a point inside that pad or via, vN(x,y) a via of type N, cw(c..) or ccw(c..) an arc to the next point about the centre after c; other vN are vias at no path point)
3V3: C11.1 C25.1 C26.1 C33.1 R17.2 R21.2 TP10.1 U3.8 U5.1 U5.7 U6.1 U6.7 U7.5 | length 3386.5
  Top Layer w11: U3.8@669.06,280 U3.8@669.49,280 ; R21.2@848.62,130 849.41,130 R21.2@849.41,125 ; C26.1@1395,298.62 1461.38,298.62 1470.59,289.41 U6.1@1470.59,267.5
  Top Layer w15: 1390,91.28 1416.22,117.5 U6.7@1470.59,117.5 ; 1395,405 1417.5,427.5 U5.7@1470.59,427.5 ; C25.1@1397.08,607.7 C25.1@1400,610.62 1401.95,610.62 1435.07,577.5 U5.1@1470.59,577.5
  Top Layer w20: U3.8@669.49,280 C11.1@802.17,280 v1(802.17,350) 802.17,472.17 TP10.1@1080,750 ; R17.2@849.41,175 849.41,130 849.41,90.59 870,70 1368.72,70 1390,91.28 ; R17.2@849.41,180 v1(1010,180) 1128.62,298.62 C26.1@1395,298.62 1395,405 ; U7.5@1268.5,761.81 C33.1@1220,761.81 1091.81,761.81 TP10.1@1080,750 ; C25.1@1397.08,607.7 1132.3,607.7 1080,660 TP10.1@1080,750
  Bottom Layer w20: v1(802.17,350) 929.82,350 1010,269.82 v1(1010,180)
5V_ISO: C10.1 C19.1 C21.1 C38.1 D14.1 D15.1 R9.2 R10.2 R12.1 R22.2 TP2.1 U1.15 U5.10 U5.16 U6.10 U6.16 | length 4011.8
  Top Layer w11: U6.10@1669.41,117.5 1721.5,117.5 1735,104 v1(1735,99) ; U5.10@1669.41,427.5 1717.5,427.5 1738.95,406.05 v1@1738.95,378.65
  Top Layer w15: U6.16@1669.41,267.5 1669.41,289.41 1692.24,312.24 C21.1@1740,312.24 ; U5.16@1669.41,577.5 1709.93,577.5 1738.05,605.62 C19.1@1740,605.62 1784.38,605.62 v1(1790,600) ; U1.15@2814.27,1240.39 2835.39,1240.39 2846.5,1251.5 C10.1@2877.93,1251.5
  Top Layer w20: C21.1@1738.95,313.3 v1@1738.95,378.65 ; C10.1@2877.93,1251.5 2909.33,1282.9 R22.2@2909.33,1307.87 v1@2957.13,1307.87
  Top Layer w50: D14.1@1710,1775.12 1735.12,1750 C38.1@1807.64,1750 1870.55,1750 D15.1@1915.02,1794.47 1915.02,1825.02 1945,1855 TP2.1@2030,1855 2035,1850 2035,1845 2131,1749 2131,1341 2202,1270 v1(2360,1270)
  Bottom Layer w50: v1(1735,99) v1@1735,374.71 ; v1@1735,382.6 1735,569 1766,600 v1(1790,600) 1870,600 1901,569 2259,569 2452,762 v1(2452,892) ; v1(2360,1270) 2360,1320.65 2439.35,1400 2867.87,1400 v1(2960,1307.87)
  other v1: 1735,378.65 2130,1452
24V_FIELD: C20.1 C22.2 C23.2 C29.1 D11.1 D12.2 J2.1
24V_LIMIT: C15.1 C17.1 C18.1 Q1.1 Q1.2 Q1.3 R27.1 R28.2 R30.2 R36.1 TP20.1 U4.2 | length 32.4
  Top Layer w11: U4.2@1275.75,1374.8 C18.1@1275.75,1407.24
  other v1: 988,1037.5 935,1071 863,1090 780,1585 855,1585 930,1585 780,1750 855,1750 930,1750
24V_PLC: D17.2 J4.35 J4.36 J4.37 J4.38 TP18.1
  other v1: 558,1171 558,1210
25V_ISO: C24.1 C37.1 D13.1 D16.1 R23.1 TP11.1 | length 1352.7
  Top Layer w50: D13.1@1710.2,840 1710.2,754.2 1809.73,754.2 ; 1810,754.47 1874.47,754.47 1930,810 2060,810 2508.54,361.46 R23.1@2508.54,200 ; C24.1@2510,100 R23.1@2510,198.54
CLK: C13.1 R19.1 U1.25 | length 181.2
  Top Layer w11: C13.1@2521.79,1366.38 2521.79,1337.21 2551.85,1307.15 ; 2551.9,1307.15 2558.37,1300.68 U1.25@2558.37,1240.39
  Top Layer w20: R19.1@2481.79,1366.38 C13.1@2521.79,1366.38
DB0: R9.1 U1.1 U6.14 | length 1454.6
  Top Layer w11: U6.14@1669.41,217.5 1712.5,217.5 1712.67,217.33 1767.67,217.33 1785,200 v1@1785,195 ; v1@2365,1006.38 R9.1@2420,1006.38 2429.61,1015.98 U1.1@2481.59,1015.98
  L3_Sig-Layer w11: v1(1790,195) 2035,195 2380,540 2380,985 v1@2360,1005
  other v1: 2365,1005
DB0_PLC: J4.27 U6.3 | length 2477
  Top Layer w11: v1(1350,195) 1372.5,217.5 U6.3@1470.59,217.5
  L3_Sig-Layer w11: v1(110,1015.73) 110,967 70,927 70,510 90,490 210,490 380,320 380,95 395,80 1275,80 1325,130 1325,180 1340,195 v1(1350,195)
  Bottom Layer w11: v1(110,1015.73) 125.77,1031.5 J4.27@261.42,1031.5
DB1: R10.1 U1.2 U6.13 | length 1452.3
  Top Layer w11: U6.13@1669.41,192.5 1747.5,192.5 1785,155 v1(1790,155) ; v1(2498.62,895) R10.1@2498.62,945 2507.18,953.56 U1.2@2507.18,1015.98
  L3_Sig-Layer w11: v1(1790,155) 2060,155 2498.62,593.62 v1(2498.62,895)
DB1_PLC: J4.29 U6.4 | length 2573.3
  Top Layer w11: v1(1350,155) 1387.5,192.5 U6.4@1470.59,192.5
  L3_Sig-Layer w11: v1(110,1062.95) 107.13,1062.95 85.7,1041.52 85.7,1040.7 40,995 40,500 80,460 200,460 355,305 355,80 385,50 1280,50 1350,120 v1(1350,155)
  Bottom Layer w11: v1(110,1062.95) J4.29@261.42,1062.99
EARTH_GND: C29.2 C31.1 J3.1 J3.2
EVM_ID_SCL: J4.12 R17.1 TP4.1 U3.6 | length 920.8
  Top Layer w11: U3.6@669.06,180 U3.6@669.49,180
  Top Layer w20: U3.6@669.49,180 v1(745.94,180) R17.1@802.17,180
  Bottom Layer w11: J4.12@438.58,779.53 542.47,779.53 705,617 TP4.1@705,400 705,220.94 v1(745.94,180)
EVM_ID_SDA: J4.11 R21.1 TP5.1 U3.5 | length 1259.2
  Top Layer w11: U3.5@669.06,130 U3.5@669.49,130
  Top Layer w20: U3.5@669.49,130 v1(745.94,130) R21.1@801.38,130
  Bottom Layer w11: J4.11@261.42,779.53 261.89,779.05 300,779.05 309.14,769.91 309.14,420.86 410,320 495,320 TP5.1@575,400 575,225 670,130 v1(745.94,130)
IP0: C1.1 R1.2 U1.3 | length 1146.4
  Top Layer w11: v1(2532.77,910) U1.3@2532.77,1015.98
  Top Layer w20: C1.1@3291.5,900 v1(3340,900) R1.2@3382.91,900
  L3_Sig-Layer w11: v1(2532.77,910) 2532.77,887.23 2670,750 3190,750 v1(3340,900)
IP0_FIELD: J1.1 R1.1 | length 152.9
  Top Layer w20: R1.1@3507.09,910 J1.1@3660,910
IP1: C2.1 R2.2 U1.5 | length 1116.6
  Top Layer w11: U1.5@2583.96,1015.98 2584.3,1015.64 v1(2584.3,910)
  Top Layer w20: C2.1@3291.5,1000 v1(3340,1000) R2.2@3382.91,1000
  L3_Sig-Layer w11: v1(2584.3,910) 2584.3,885.7 2695,775 3115,775 v1(3340,1000)
IP1_FIELD: J1.2 R2.1 | length 152.9
  Top Layer w20: R2.1@3507.09,1010 J1.2@3660,1010
IP2: C3.1 R3.2 U1.7 | length 1086.9
  Top Layer w11: v1(2635,910) 2635.14,910.14 U1.7@2635.14,1015.98
  Top Layer w20: C3.1@3291.5,1100 v1(3340,1100) R3.2@3382.91,1100
  L3_Sig-Layer w11: v1(2635,910) 2635,885 2720,800 2960,800 3060,900 3140,900 v1(3340,1100)
IP2_FIELD: J1.3 R3.1 | length 152.9
  Top Layer w20: R3.1@3507.09,1110 J1.3@3660,1110
IP3: C4.1 R4.2 U1.9 | length 1057
  Top Layer w11: v1(2686.32,910) U1.9@2686.32,1015.98
  Top Layer w20: C4.1@3291.5,1200 v1(3340,1200) R4.2@3382.91,1200
  L3_Sig-Layer w11: v1(2686.32,910) 2686.32,883.68 2745,825 2915,825 3290,1200 v1(3340,1200)
IP3_FIELD: J1.4 R4.1 | length 152.9
  Top Layer w20: R4.1@3507.09,1210 J1.4@3660,1210
IP4: C5.1 R5.2 U1.11 | length 983.8
  Top Layer w11: v1@2737.5,912.5 U1.11@2737.5,1015.98
  Top Layer w20: C5.1@3291.5,1300 v1(3340,1300) R5.2@3382.91,1300
  L3_Sig-Layer w11: v1(2737.5,910) 2767.5,880 2875,880 3100,1105 3145,1105 v1(3340,1300)
IP4_FIELD: J1.5 R5.1 | length 152.9
  Top Layer w20: R5.1@3507.09,1310 J1.5@3660,1310
IP5: C6.1 R6.2 U1.18 | length 845.7
  Top Layer w11: U1.18@2737.5,1240.39 v1(2737.5,1325)
  Top Layer w20: C6.1@3291.5,1400 v1(3340,1400) 3382.91,1400 R6.2@3392.91,1410
  L3_Sig-Layer w11: v1(2737.5,1325) 2737.5,1362.5 2775,1400 v1(3340,1400)
IP5_FIELD: J1.6 R6.1 | length 152.9
  Top Layer w20: R6.1@3507.09,1410 J1.6@3660,1410
IP6: C7.1 R7.2 U1.20 | length 923.5
  Top Layer w11: U1.20@2686.32,1240.39 v1(2686.32,1325)
  Top Layer w20: C7.1@3291.5,1500 v1(3340,1500) R7.2@3382.91,1500
  L3_Sig-Layer w11: v1(2686.32,1325) 2686.32,1361.32 2825,1500 v1(3340,1500)
IP6_FIELD: J1.7 R7.1 | length 152.9
  Top Layer w20: R7.1@3507.09,1510 J1.7@3660,1510
IP7: C8.1 R8.2 U1.22 | length 1037.4
  Top Layer w11: U1.22@2635.14,1240.39 v1(2635.14,1325)
  Top Layer w20: C8.1@3287.09,1600 v1(3340,1600) R8.2@3382.91,1600
  L3_Sig-Layer w11: v1(2635.14,1325) 2635.14,1390.14 2845,1600 v1(3340,1600)
IP7_FIELD: J1.8 R8.1 | length 152.9
  Top Layer w20: R8.1@3507.09,1610 J1.8@3660,1610
ISO_GND: C1.2 C2.2 C3.2 C4.2 C5.2 C6.2 C7.2 C8.2 C10.2 C12.2 C13.2 C14.2 C16.2 C19.2 C20.2 C21.2 C24.2 C31.2 C32.1 C37.2 C38.2 D1.2 D2.2 D3.2 D4.2 D5.2 D6.2 D7.2 D8.2 D12.1 D15.2 D16.2 J2.2 R11.1 T1.4 TP1.1 TP3.1 TP13.1 U1.28 U1.29 U5.9 U5.15 U6.9 U6.15 | length 2475.1
  Top Layer w11: U6.15@1669.41,242.5 1717.5,242.5 C21.2@1740,265 1775,265 1775,264 v1(1790,249) ; U5.15@1669.41,552.5 1736.12,552.5 1740,556.38 v1@1788.62,556.38 ; v1@2430,1286 2432,1288 2471,1288 2481.59,1277.41 U1.28@2481.59,1240.39 ; C12.2@2600,1415.41 C12.2@2601.79,1413.62
  Top Layer w15: v1@1669.41,45.59 U6.9@1669.41,92.5 ; v1@1669.41,355.59 U5.9@1669.41,402.5
  Top Layer w20: C16.2@1795,346.38 v1@1838.62,346.38 ; C14.2@2441.79,1413.62 v1@2441.79,1463.21 ; C13.2@2521.79,1413.62 v1@2521.79,1463.21 ; C12.2@2601.79,1417.2 v1(2601.79,1465) ; v1(3090,1143.68) 3090,1193.94 3096.06,1200 C4.2@3172.91,1200 ; D1.2@3091.66,890 3101.66,900 C1.2@3178.51,900 ; D2.2@3091.66,990 3101.66,1000 C2.2@3178.51,1000 ; D3.2@3091.66,1090 3101.66,1100 C3.2@3178.51,1100 ; D5.2@3091.66,1290 3091.66,1297.1 3094.57,1300 C5.2@3171.42,1300 ; D6.2@3091.66,1390 3101.66,1400 C6.2@3178.51,1400 ; v1(3091.66,1524.74) D7.2@3091.66,1490 3101.66,1500 C7.2@3178.51,1500 ; D8.2@3091.66,1590.02 3101.66,1600.02 C8.2@3178.51,1600.02
  Top Layer w22: R11.1@2853.52,951.12 v1@2899.84,951.12 ; v1(2877.93,1160) C10.2@2877.93,1204.25 ; v1(3091.66,855) D1.2@3091.66,890 ; v1@3091.66,943.68 D2.2@3091.66,990 ; v1(3091.66,1045.75) D3.2@3091.66,1090 ; v1(3091.66,1243.68) D5.2@3091.66,1290 ; D6.2@3091.66,1390 v1(3091.66,1425) ; D8.2@3091.66,1590.02 v1@3091.66,1636.34
  Top Layer w30: C38.2@1807.64,1665.53 D15.2@1915.02,1665.53 2019.47,1665.53 TP13.1@2030,1655
  Top Layer w45: T1.4@1807.64,1580 C38.2@1807.64,1665.53
  Top Layer w50: C32.1@1627.09,720 1675.29,671.8 C37.2@1707.8,671.8 1783.73,671.8 1820,635.53 1940.53,635.53 TP1.1@1960,655
  other v1: 1670,45 2660,75 2857,119 2660,120 2857,166 1840,346.38 1670,355 1790,555 3091.66,945.75 2897.77,951.12 2429,1289 2441.79,1465 2521.79,1465 3091.66,1634.27
  other v2: 2549.51,1088.82 2588.88,1088.82 2628.25,1088.82 2667.62,1088.82 2706.99,1088.82 2746.36,1088.82 2549.51,1128.19 2588.88,1128.19 2628.25,1128.19 2667.62,1128.19 2706.99,1128.19 2746.36,1128.19 2549.51,1167.56 2588.88,1167.56 2628.25,1167.56 2667.62,1167.56 2706.99,1167.56 2746.36,1167.56
MISO: J4.5 U5.6 | length 1769.4
  Top Layer w11: v1(1360,420) 1392.5,452.5 U5.6@1470.59,452.5
  L3_Sig-Layer w11: v1(110,560) 145,595 425,595 490,530 760,530 870,420 v1(1360,420)
  Bottom Layer w11: v1(110,560) 75,595 75,655 105.04,685.04 J4.5@261.42,685.04
MISO_ISO: C16.1 R16.2 TP9.1 U5.11 | length 341.9
  Top Layer w11: U5.11@1669.41,452.5 1743.88,452.5 R16.2@1746.38,450 C16.1@1795,401.38 ; C16.1@1795,393.62 1921.38,393.62 TP9.1@1970,345
NCE: C12.1 R18.1 U1.24 | length 175.2
  Top Layer w11: R18.1@2561.79,1366.38 2561.79,1324.21 2570.7,1315.3 2570.7,1314.93 2583.96,1301.68 U1.24@2583.96,1240.39
  Top Layer w20: R18.1@2561.79,1366.38 C12.1@2601.79,1366.38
